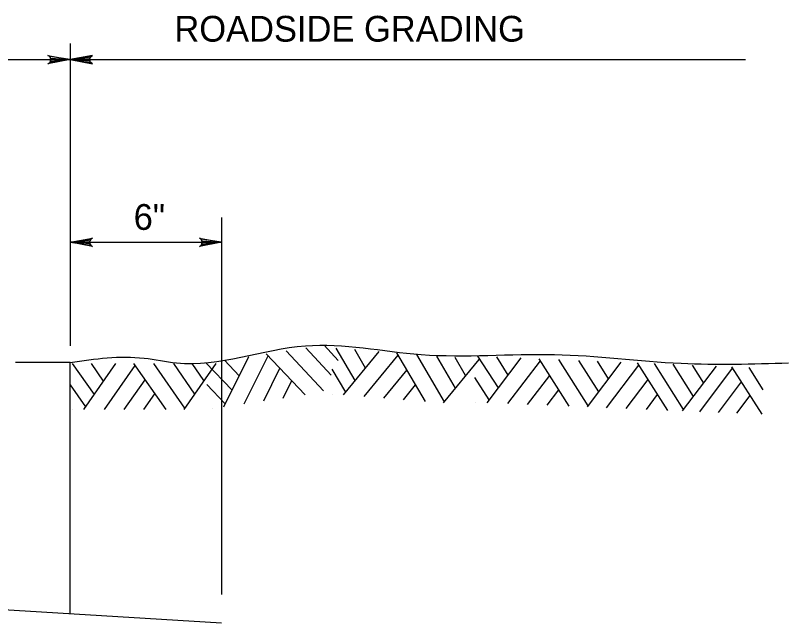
# Model space of a CAD drawing. Extents: x -0.97 to 5.98, y -2.63 to 7.27.
# Drawn here: x 3.389 to 5.188, y 5.867 to 7.27 of the extents above; entities that cross this region are included whole.
import ezdxf

# ---------------------------------------------------------------- set-up
doc = ezdxf.new("R2010")
doc.units = 0
for name, color, linetype in [('DETL-DIMS', 7, 'Continuous'), ('DETL-LINE', 7, 'Continuous'), ('DETL-NOTE', 7, 'Continuous'), ('DETL-PATT', 7, 'Continuous')]:
    doc.layers.add(name, color=color, linetype=linetype)

msp = doc.modelspace()

# ---------------------------------------------------------------- linework, layer by layer
at = {"layer": 'DETL-DIMS'}
for p, q in [((3.5162, 7.2048), (3.5162, 6.5019)), ((-0.8117, 7.1678), (5.0884, 7.1678)), ((3.8687, 6.8), (3.8687, 5.9229)), ((3.5162, 6.7426), (3.8687, 6.7426))]:
    msp.add_line(p, q, dxfattribs=at)
for points in [[(3.5162, 7.1678), (3.4644, 7.1581), (3.4684, 7.1608), (3.4704, 7.1643), (3.471, 7.1678), (3.4704, 7.1713), (3.4684, 7.1747), (3.4644, 7.1775), (3.5162, 7.1678), (3.4684, 7.1747), (3.4704, 7.1713), (3.5162, 7.1678), (3.471, 7.1678), (3.4704, 7.1643), (3.5162, 7.1678), (3.4684, 7.1608)], [(3.5162, 7.1678), (3.4644, 7.1581), (3.4684, 7.1608), (3.4704, 7.1643), (3.471, 7.1678), (3.4704, 7.1713), (3.4684, 7.1747), (3.4644, 7.1775), (3.5162, 7.1678), (3.4684, 7.1747), (3.4704, 7.1713), (3.5162, 7.1678), (3.471, 7.1678), (3.4704, 7.1643), (3.5162, 7.1678), (3.4684, 7.1608)], [(3.5162, 7.1678), (3.5679, 7.1581), (3.564, 7.1608), (3.5619, 7.1643), (3.5613, 7.1678), (3.5619, 7.1713), (3.564, 7.1747), (3.5679, 7.1775), (3.5162, 7.1678), (3.564, 7.1747), (3.5619, 7.1713), (3.5162, 7.1678), (3.5613, 7.1678), (3.5619, 7.1643), (3.5162, 7.1678), (3.564, 7.1608)], [(3.5162, 6.7426), (3.5679, 6.7523), (3.564, 6.7496), (3.5619, 6.7461), (3.5613, 6.7426), (3.5619, 6.7391), (3.564, 6.7357), (3.5679, 6.7329), (3.5162, 6.7426), (3.564, 6.7357), (3.5619, 6.7391), (3.5162, 6.7426), (3.5613, 6.7426), (3.5619, 6.7461), (3.5162, 6.7426), (3.564, 6.7496)], [(3.8687, 6.7426), (3.8169, 6.7329), (3.8209, 6.7357), (3.8229, 6.7391), (3.8235, 6.7426), (3.8229, 6.7461), (3.8209, 6.7496), (3.8169, 6.7523), (3.8687, 6.7426), (3.8209, 6.7496), (3.8229, 6.7461), (3.8687, 6.7426), (3.8235, 6.7426), (3.8229, 6.7391), (3.8687, 6.7426), (3.8209, 6.7357)], [(3.8687, 6.7426), (3.8169, 6.7329), (3.8209, 6.7357), (3.8229, 6.7391), (3.8235, 6.7426), (3.8229, 6.7461), (3.8209, 6.7496), (3.8169, 6.7523), (3.8687, 6.7426), (3.8209, 6.7496), (3.8229, 6.7461), (3.8687, 6.7426), (3.8235, 6.7426), (3.8229, 6.7391), (3.8687, 6.7426), (3.8209, 6.7357)]]:
    msp.add_lwpolyline(points, dxfattribs=at)
at = {"layer": 'DETL-LINE'}
for p, q in [((3.5162, 6.4628), (3.3888, 6.4628)), ((3.5162, 5.8777), (3.5162, 6.4628)), ((3.8687, 5.8562), (-0.0802, 6.0971))]:
    msp.add_line(p, q, dxfattribs=at)
msp.add_spline([(3.5162, 6.4628), (3.6884, 6.4729), (3.7637, 6.4616), (4.0635, 6.5017), (4.3329, 6.4814), (4.6431, 6.4814), (4.938, 6.461), (5.1882, 6.4617)], degree=3, dxfattribs=at)
at = {"layer": 'DETL-PATT'}
for p, q in [((4.1239, 6.4336), (4.0648, 6.4966)), ((4.14, 6.4677), (4.1074, 6.503)), ((4.1797, 6.4205), (4.1351, 6.4964)), ((3.9213, 6.3665), (3.9769, 6.4784)), ((4.0629, 6.3877), (3.9727, 6.4829)), ((4.106, 6.3972), (4.0188, 6.4898)), ((4.1524, 6.3872), (4.2354, 6.4884)), ((4.2036, 6.4498), (4.179, 6.4929)), ((4.2003, 6.3834), (4.2799, 6.4798)), ((4.3431, 6.372), (4.2768, 6.4851)), ((4.3872, 6.3714), (4.3232, 6.4814)), ((3.5725, 6.3884), (3.5219, 6.4605)), ((3.5479, 6.3531), (3.6225, 6.4605)), ((3.594, 6.4195), (3.5659, 6.4605)), ((3.7392, 6.3531), (3.6641, 6.4605)), ((3.7832, 6.3561), (3.7106, 6.4605)), ((3.8063, 6.3894), (3.7572, 6.4605)), ((3.7812, 6.3531), (3.8558, 6.4605)), ((3.8273, 6.4208), (3.8003, 6.4605)), ((3.8928, 6.398), (3.8321, 6.4619)), ((3.8737, 6.3594), (3.9316, 6.4767)), ((3.9095, 6.4319), (3.8757, 6.4684)), ((4.4129, 6.4029), (4.3696, 6.4777)), ((4.385, 6.3686), (4.4679, 6.4698)), ((4.4363, 6.4325), (4.4125, 6.4742)), ((4.5128, 6.4035), (4.4653, 6.4776)), ((4.4868, 6.3691), (4.5658, 6.4734)), ((4.5356, 6.4336), (4.5093, 6.4758)), ((4.5348, 6.3671), (4.6106, 6.4665)), ((4.6779, 6.3611), (4.6074, 6.4716)), ((4.722, 6.3622), (4.6539, 6.4697)), ((4.7464, 6.3946), (4.7004, 6.4677)), ((4.7199, 6.3593), (4.7989, 6.4636)), ((4.7688, 6.4251), (4.7434, 6.4659)), ((4.9075, 6.3514), (4.8365, 6.462)), ((4.9441, 6.3532), (4.876, 6.4603)), ((3.596, 6.3531), (3.6676, 6.4555)), ((3.9668, 6.3733), (4.0045, 6.4495)), ((4.1575, 6.3935), (4.1261, 6.4469)), ((4.2463, 6.3797), (4.3002, 6.4454)), ((4.7644, 6.3574), (4.8397, 6.4565)), ((4.967, 6.3833), (4.9195, 6.4585)), ((4.9415, 6.35), (5.0206, 6.4546)), ((4.9908, 6.4147), (4.9645, 6.4566)), ((4.9815, 6.3483), (5.0579, 6.4493)), ((5.1266, 6.3422), (5.0566, 6.4527)), ((5.129, 6.3995), (5.0966, 6.451)), ((4.4916, 6.3756), (4.4582, 6.4278)), ((4.5808, 6.3652), (4.6323, 6.4328)), ((3.5524, 6.3597), (3.5169, 6.4105)), ((3.6421, 6.3531), (3.6906, 6.4228)), ((3.8772, 6.3667), (3.8345, 6.4116)), ((4.0119, 6.3801), (4.0317, 6.4205)), ((4.2917, 6.3761), (4.3201, 6.411)), ((4.8104, 6.3555), (4.8614, 6.4232)), ((5.0255, 6.3464), (5.0786, 6.4174)), ((3.6876, 6.3531), (3.7132, 6.3901)), ((4.1262, 6.3893), (4.1262, 6.3893)), ((4.6263, 6.3633), (4.6534, 6.3992)), ((4.8575, 6.3535), (4.8835, 6.3885)), ((4.4605, 6.3702), (4.4605, 6.3702)), ((5.0681, 6.3447), (5.0989, 6.3858)), ((3.5216, 6.3531), (3.5216, 6.3531)), ((3.8477, 6.3555), (3.8477, 6.3555))]:
    msp.add_line(p, q, dxfattribs=at)

# ---------------------------------------------------------------- texts
at = {"layer": 'DETL-NOTE'}
for s, p in [('ROADSIDE GRADING', (3.7587, 7.2094)), ('6"', (3.6639, 6.7714))]:
    msp.add_text(s, height=0.06, dxfattribs=at).set_placement(p)

doc.saveas('drawing.dxf')
